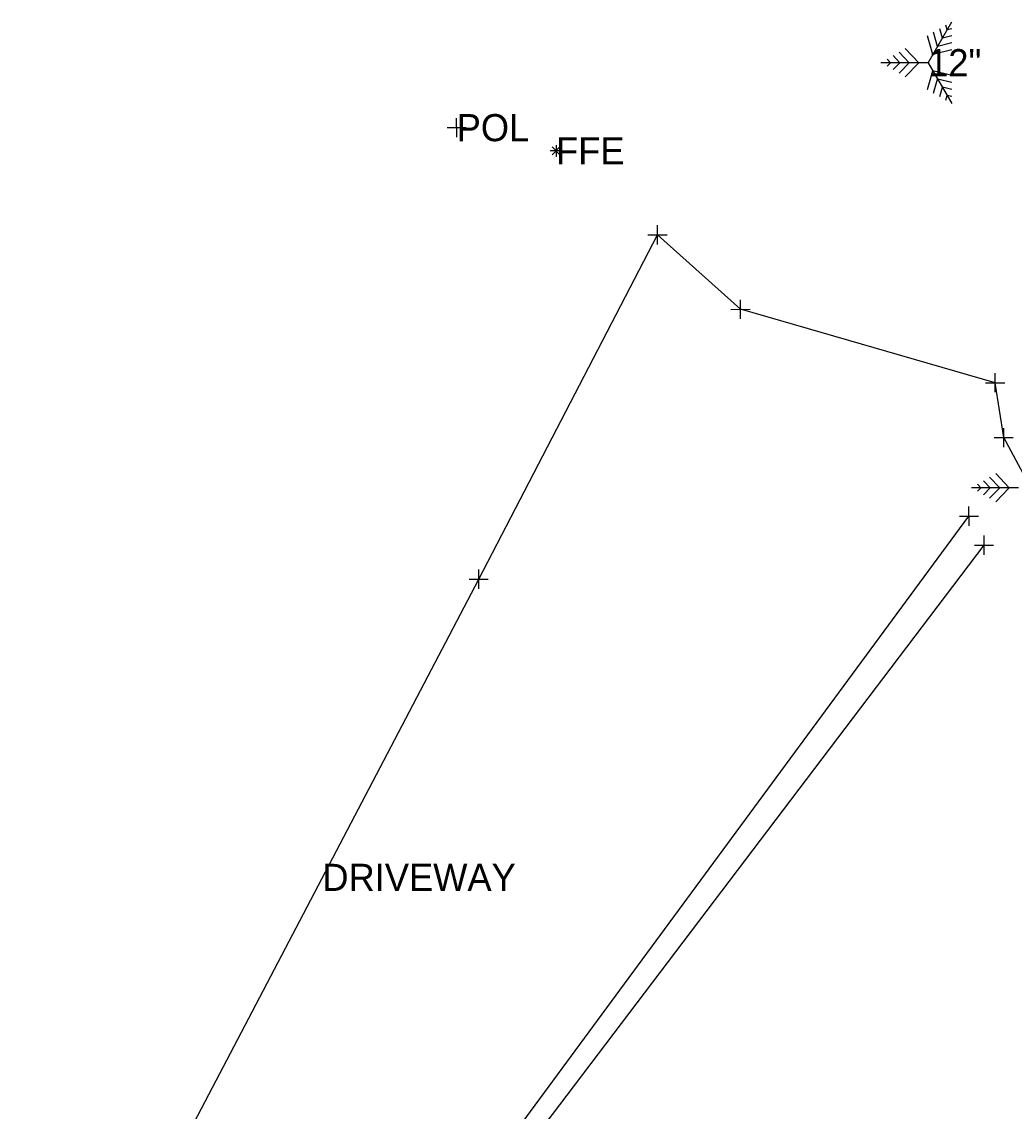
# Model space of a CAD drawing. Extents: x 1729655 to 1739338, y 463812 to 469501.
# Drawn here: x 1734846.2 to 1734912.1, y 466865.3 to 466937.7 of the extents above; entities that cross this region are included whole.
import ezdxf

# ---------------------------------------------------------------- set-up
doc = ezdxf.new("R2010")
doc.units = 0
for name, color, linetype in [('S_Bridge_Column_Round', 7, 'Continuous'), ('S_Buildings_Steps', 7, 'Continuous'), ('S_Drainage_Invert_Culvert', 7, 'Continuous'), ('S_Fencing_ChainLink', 7, 'Continuous'), ('S_Ground_SpotElevation', 7, 'Continuous'), ('S_Terrain_High_Points', 7, 'Continuous'), ('S_Traffic_Posts', 7, 'Continuous'), ('S_Utilities_Pole_StreetLight', 7, 'Continuous')]:
    doc.layers.add(name, color=color, linetype=linetype)

msp = doc.modelspace()

# ---------------------------------------------------------------- linework, layer by layer
at = {"layer": 'S_Bridge_Column_Round'}
for p, q in [((1734875.062, 466930.016), (1734875.06, 466931.288)), ((1734874.425, 466930.651), (1734875.697, 466930.653)), ((1734875.061, 466930.652), (1734875.061, 466930.652)), ((1734888.394, 466922.903), (1734888.392, 466924.175)), ((1734888.394, 466922.903), (1734888.392, 466924.175)), ((1734888.394, 466922.903), (1734888.392, 466924.175)), ((1734887.757, 466923.538), (1734889.029, 466923.54)), ((1734887.757, 466923.538), (1734889.029, 466923.54)), ((1734887.757, 466923.538), (1734889.029, 466923.54)), ((1734888.393, 466923.539), (1734888.393, 466923.539)), ((1734888.393, 466923.539), (1734888.393, 466923.539)), ((1734888.393, 466923.539), (1734888.393, 466923.539)), ((1734893.901, 466917.953), (1734893.899, 466919.225)), ((1734893.264, 466918.588), (1734894.536, 466918.59)), ((1734893.9, 466918.589), (1734893.9, 466918.589)), ((1734910.818, 466913.081), (1734910.816, 466914.353)), ((1734910.181, 466913.716), (1734911.453, 466913.718)), ((1734910.817, 466913.717), (1734910.817, 466913.717)), ((1734911.381, 466909.436), (1734911.379, 466910.708)), ((1734910.744, 466910.071), (1734912.016, 466910.073)), ((1734911.38, 466910.072), (1734911.38, 466910.072)), ((1734909.076, 466904.221), (1734909.073, 466905.494)), ((1734908.438, 466904.856), (1734909.711, 466904.859)), ((1734909.074, 466904.858), (1734909.074, 466904.858)), ((1734910.077, 466902.294), (1734910.075, 466903.566)), ((1734909.44, 466902.928), (1734910.712, 466902.931)), ((1734910.076, 466902.93), (1734910.076, 466902.93)), ((1734876.525, 466900.041), (1734876.523, 466901.313)), ((1734875.888, 466900.676), (1734877.16, 466900.678)), ((1734876.524, 466900.677), (1734876.524, 466900.677))]:
    msp.add_line(p, q, dxfattribs=at)
at = {"layer": 'S_Buildings_Steps'}
for p, q in [((1734881.657, 466929.5), (1734881.657, 466928.714)), ((1734882.05, 466929.107), (1734881.264, 466929.107)), ((1734881.919, 466928.845), (1734881.395, 466929.369)), ((1734881.919, 466929.369), (1734881.395, 466928.845))]:
    msp.add_line(p, q, dxfattribs=at)
at = {"layer": 'S_Drainage_Invert_Culvert'}
msp.add_lwpolyline([(1734939.861, 466905.708), (1734937.89, 466910.409), (1734933.486, 466912.388), (1734921.073, 466910.85), (1734919.15, 466908.643), (1734915.596, 466902.246), (1734911.38, 466910.072), (1734910.817, 466913.717), (1734893.9, 466918.589), (1734888.393, 466923.539)], dxfattribs=at)
at = {"layer": 'S_Fencing_ChainLink'}
for p, q in [((1734906.364, 466934.965), (1734907.934, 466937.681)), ((1734907.62, 466937.138), (1734907.531, 466937.45)), ((1734906.678, 466935.508), (1734906.322, 466936.752)), ((1734906.992, 466936.051), (1734906.725, 466936.985)), ((1734907.306, 466936.595), (1734907.128, 466937.218)), ((1734907.934, 466936.752), (1734907.306, 466936.595)), ((1734907.934, 466937.218), (1734907.62, 466937.138)), ((1734907.934, 466936.285), (1734906.992, 466936.051)), ((1734904.484, 466934.965), (1734904.034, 466935.432)), ((1734905.11, 466934.965), (1734904.437, 466935.665)), ((1734905.736, 466934.965), (1734904.841, 466935.899)), ((1734907.934, 466935.82), (1734906.678, 466935.508)), ((1734906.364, 466934.965), (1734903.228, 466934.965)), ((1734903.856, 466934.965), (1734903.631, 466935.198)), ((1734903.631, 466934.734), (1734903.856, 466934.965)), ((1734904.034, 466934.502), (1734904.484, 466934.965)), ((1734904.437, 466934.269), (1734905.11, 466934.965)), ((1734904.841, 466934.036), (1734905.736, 466934.965)), ((1734906.364, 466934.965), (1734907.934, 466932.249)), ((1734906.322, 466933.183), (1734906.678, 466934.422)), ((1734907.934, 466934.112), (1734906.678, 466934.422)), ((1734906.725, 466932.949), (1734906.992, 466933.879)), ((1734907.934, 466933.647), (1734906.992, 466933.879)), ((1734907.128, 466932.716), (1734907.306, 466933.335)), ((1734907.934, 466933.183), (1734907.306, 466933.335)), ((1734907.531, 466932.483), (1734907.62, 466932.792)), ((1734907.934, 466932.716), (1734907.62, 466932.792)), ((1734910.49, 466906.744), (1734910.04, 466907.211)), ((1734911.116, 466906.744), (1734910.443, 466907.444)), ((1734911.742, 466906.744), (1734910.847, 466907.678)), ((1734912.37, 466906.744), (1734909.234, 466906.744)), ((1734909.862, 466906.744), (1734909.637, 466906.977)), ((1734909.637, 466906.513), (1734909.862, 466906.744)), ((1734910.04, 466906.281), (1734910.49, 466906.744)), ((1734910.443, 466906.048), (1734911.116, 466906.744)), ((1734910.847, 466905.815), (1734911.742, 466906.744))]:
    msp.add_line(p, q, dxfattribs=at)
at = {"layer": 'S_Ground_SpotElevation'}
msp.add_lwpolyline([(1734843.853, 466838.233), (1734856.9, 466863.197), (1734876.524, 466900.677), (1734888.393, 466923.539)], dxfattribs=at)
at = {"layer": 'S_Traffic_Posts'}
msp.add_lwpolyline([(1734857.999, 466759.987), (1734848.577, 466809.422), (1734867.053, 466846.173), (1734910.076, 466902.93)], dxfattribs=at)
at = {"layer": 'S_Utilities_Pole_StreetLight'}
msp.add_lwpolyline([(1734857.148, 466759.709), (1734846.931, 466809.919), (1734863.973, 466843.592), (1734909.074, 466904.858)], dxfattribs=at)

# ---------------------------------------------------------------- texts
at = {"layer": 'S_Terrain_High_Points'}
for s, p in [('12"', (1734906.364, 466934.065)), ('POL', (1734875.061, 466929.752)), ('FFE', (1734881.657, 466928.207)), ('DRIVEWAY', (1734866.146, 466879.974))]:
    msp.add_text(s, height=1.8, dxfattribs=at).set_placement(p)

doc.saveas('drawing.dxf')
